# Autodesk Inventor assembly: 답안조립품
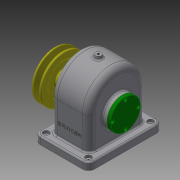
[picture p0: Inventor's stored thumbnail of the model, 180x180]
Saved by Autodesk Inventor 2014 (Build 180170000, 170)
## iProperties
Created: 2016-10
Part Number: 답안조립품
Document SubType Name: Assembly
Designer: USER
Author: USER
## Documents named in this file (13)
- C:\Users\USER\Desktop\461008V1015\답안조립품.iam
- C:\Users\USER\Desktop\461008V1015\본체.ipt
- C:\Users\USER\Desktop\461008V1015\베어링 6203.ipt
- C:\Users\USER\Desktop\461008V1015\축.ipt
- C:\Users\USER\Desktop\461008V1015\키 - 6 x 6 x 22.ipt
- C:\Users\USER\Desktop\461008V1015\스퍼기어.ipt
- C:\Users\USER\Desktop\461008V1015\뒤커버.ipt
- C:\Users\USER\Desktop\461008V1015\앞커버.ipt
- C:\Users\USER\Desktop\461008V1015\오일씰 28 40 8.ipt
- C:\Users\USER\Desktop\461008V1015\부시.ipt
- C:\Users\USER\Desktop\461008V1015\V-벨트풀리.ipt
- C:\Users\USER\Desktop\461008V1015\키 - 5 x 5 x 18.ipt
- C:\Users\USER\Desktop\461008V1015\멈춤나사 - M4x10.ipt
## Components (1 placed, 1 different names)
1. V-벨트풀리:1
